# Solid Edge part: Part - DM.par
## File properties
Author: hhakima
Template: Normal.par
Last saved by: hhakima
Revision: 7
Application: Solid Edge
Density: 2595.000 kg/m^3
Accuracy: 0.990
Material: Glass, general industrial
Face Style: White (glass)
Fill Style: ANSI36(Marble)
Virtual Style: White (Glass)
Coef. of Thermal Exp: 0.0
Thermal Conductivity: 0.0
Specific Heat: 0.0
Modulus of Elasticity: 0.0
Poission's Ratio: 0.0
Yield Stress: 0.0
Ultimate Stress: 0.0
Elongation: 0.0
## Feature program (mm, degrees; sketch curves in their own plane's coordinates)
sketch for "unnamed Protrusion 1" plane through (0, 0, 0) normal (0, -1, 0) x-axis (1, 0, 0)
  circle centre (0, 0) radius 6.25
extrude "unnamed Protrusion 1" add finite 1.05 along -normal
fillet "Round_1" radius 0.1
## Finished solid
Body 1: solid body, 5 faces, 4 edges, 0 vertices.
  Faces by surface: plane 2, torus 2, cylinder 1
  Edges by curve: circle 4
Bounding box of the edges (mm; curved faces can reach further): 12.500 x 1.050 x 12.500, from (-6.25, 0, -6.25) to (6.25, 1.05, 6.25).
Cylindrical faces by radius (mm): R6.25 x1
Toroidal faces (ring radius, tube radius in mm): R6.15 r0.1 x2
Planar faces by outward normal: +y 1, -y 1
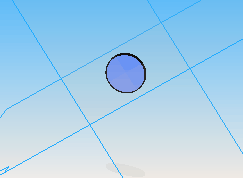
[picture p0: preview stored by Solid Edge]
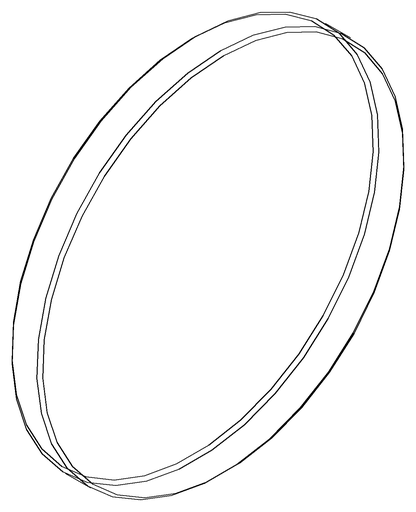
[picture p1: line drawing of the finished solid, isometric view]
